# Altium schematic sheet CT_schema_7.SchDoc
size 287 x 163 mm
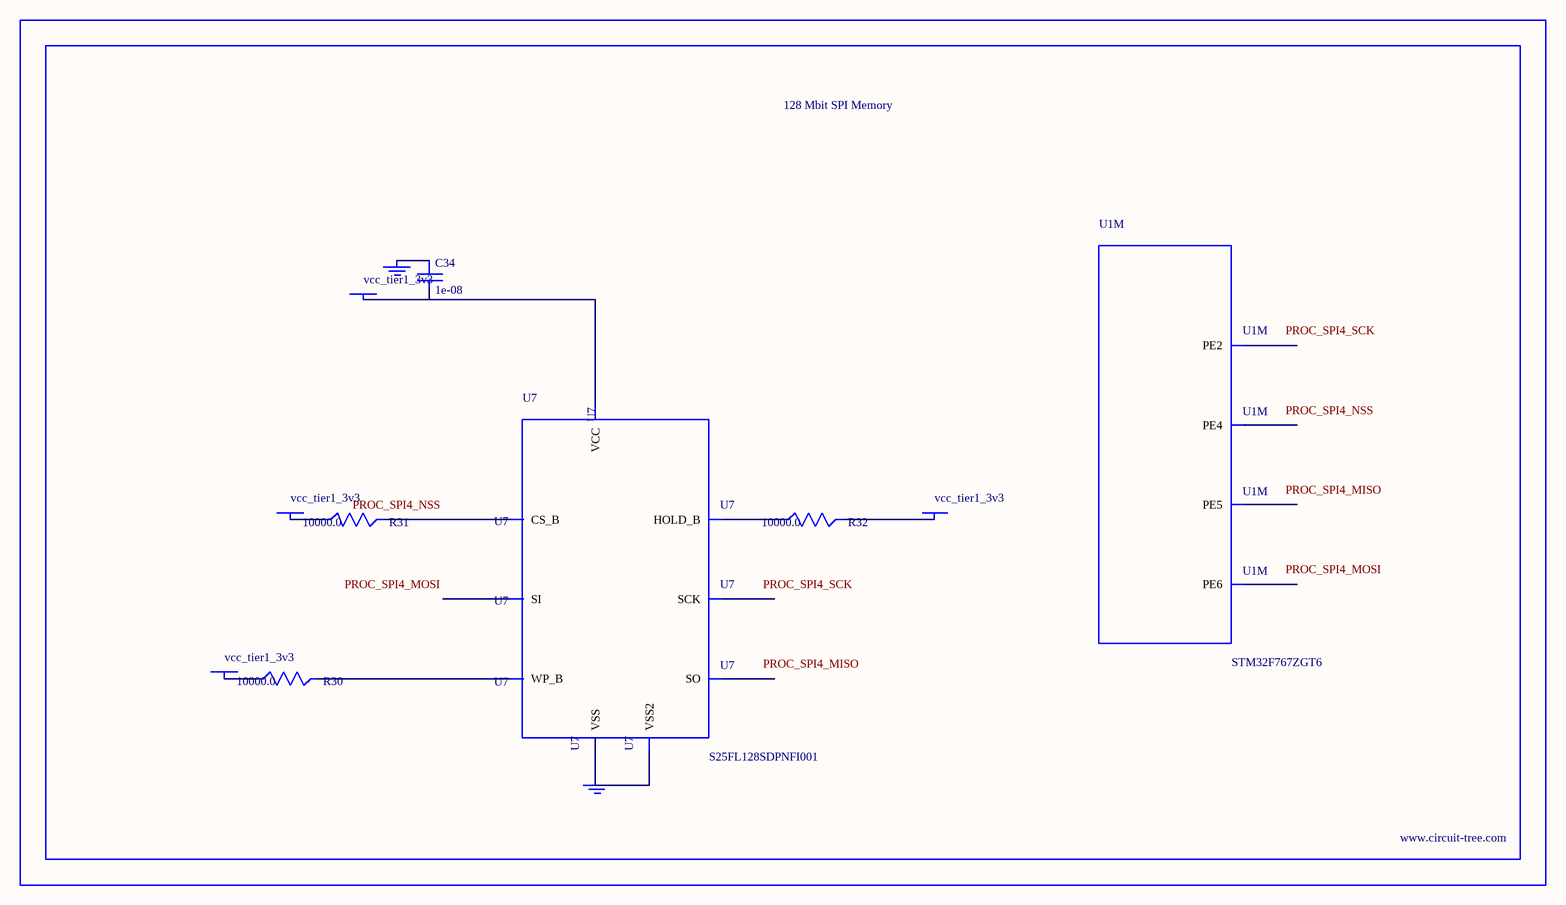
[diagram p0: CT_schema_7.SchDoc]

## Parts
BORDER6  (no value)
C34  1e-08  [C0402]
GND_INSTANCE_6_0  (no value)
GND_INSTANCE_6_1  (no value)
POWER_INSTANCE_6_0  vcc_tier1_3v3
POWER_INSTANCE_6_1  vcc_tier1_3v3
POWER_INSTANCE_6_2  vcc_tier1_3v3
POWER_INSTANCE_6_3  vcc_tier1_3v3
R30  10000.0  [R0603]
R31  10000.0  [R0603]
R32  10000.0  [R0603]
U1  STM32F767ZGT6  [LQFP144]  (part M of 13)
U7  S25FL128SDPNFI001  [WNG008]

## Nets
NetC34_1: C34.1 GND_INSTANCE_6_0.0(GND)
NetC34_2: C34.2 POWER_INSTANCE_6_3.0(PWR) U7.8(VCC)
NetGND_INSTANCE_6_1_0: GND_INSTANCE_6_1.0(GND) U7.4(VSS) U7.PAD(VSS2)
NetPOWER_INSTANCE_6_0_0: POWER_INSTANCE_6_0.0(PWR) R31.1
NetPOWER_INSTANCE_6_1_0: POWER_INSTANCE_6_1.0(PWR) R30.1
NetPOWER_INSTANCE_6_2_0: POWER_INSTANCE_6_2.0(PWR) R32.2
NetR30_2: R30.2 U7.3(WP_B)
NetR31_2: R31.2 U7.1(CS_B)
NetR32_1: R32.1 U7.7(HOLD_B)

Not connected (* = marked no-connect by the designer): U1 1(PE2) 3(PE4) 4(PE5) 5(PE6); U7 2(SO) 5(SI) 6(SCK)

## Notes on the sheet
- Labels drawn without touching a wire or pin: PROC_SPI4_MISO, PROC_SPI4_MOSI, PROC_SPI4_NSS, PROC_SPI4_SCK

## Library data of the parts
BORDER6 = BORDER_PAGE6
C34 = C0402C103K3RAC
GND_INSTANCE_6_0 GND_INSTANCE_6_1 = GND
POWER_INSTANCE_6_0-POWER_INSTANCE_6_3 = PWR
R30-R32 = RC0603JR-0710KL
